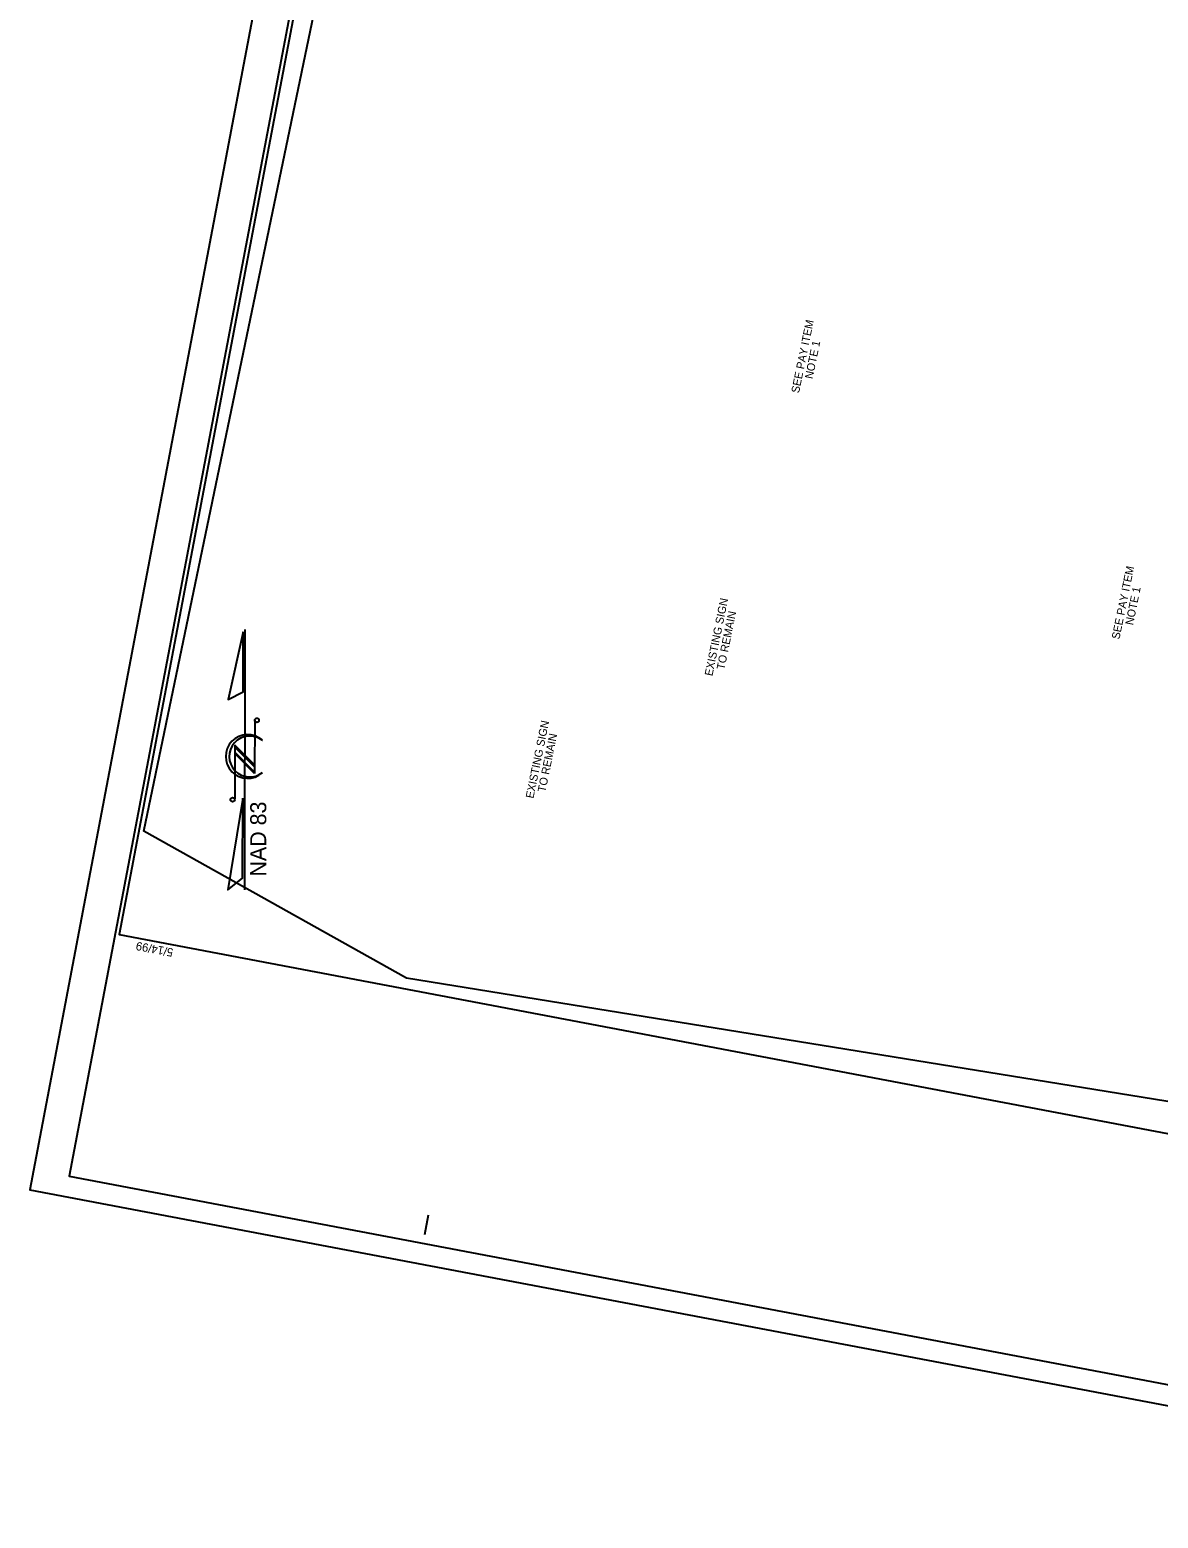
# Model space of a CAD drawing. Extents: x 1615681 to 1617075, y 899309 to 901168.
# Drawn here: x 1615681 to 1616385, y 899309 to 900239 of the extents above; entities that cross this region are included whole.
import ezdxf

# ---------------------------------------------------------------- set-up
doc = ezdxf.new("R2010")
doc.units = 0
for name, color, linetype in [('CTL Primary Horizontal and Vertical CELL', 7, 'Continuous'), ('CTL Primary Horizontal and Vertical Cogo Number', 7, 'Continuous'), ('CTL Secondary Horizontal and Vertical CELL', 7, 'Continuous'), ('Default', 7, 'Continuous'), ('Exist DTM Crownline Cogo Number', 7, 'Continuous'), ('Exist DTM Drainline Cogo Point CELL', 7, 'Continuous')]:
    doc.layers.add(name, color=color, linetype=linetype)

msp = doc.modelspace()

# ---------------------------------------------------------------- linework, layer by layer
at = {"layer": 'CTL Primary Horizontal and Vertical CELL'}
msp.add_lwpolyline([(1616015.87, 901159.82), (1615705.01, 899522.57), (1616741.59, 899325.76), (1617052.45, 900963.01)], close=True, dxfattribs=at)
at = {"layer": 'CTL Primary Horizontal and Vertical Cogo Number'}
msp.add_lwpolyline([(1615994.65, 901168.43), (1615680.53, 899513.99), (1616761.22, 899308.8), (1617075.34, 900963.24)], close=True, dxfattribs=at)
at = {"layer": 'CTL Secondary Horizontal and Vertical CELL'}
for p, q in [((1615736.43, 899674.38), (1615736.43, 899674.38)), ((1615927.13, 899486), (1615929.47, 899498.28))]:
    msp.add_line(p, q, dxfattribs=at)
msp.add_lwpolyline([(1616016.04, 901147.07), (1615736.24, 899673.39), (1616767.81, 899477.53), (1617047.61, 900951.21)], close=True, dxfattribs=at)
at = {"layer": 'Exist DTM Crownline Cogo Number'}
msp.add_lwpolyline([(1616176.29, 901060.7), (1617032.97, 900874.07), (1616753.23, 899510.43), (1615915.8, 899646.19), (1615751.76, 899738.03), (1615999.36, 900929.08), (1616157.93, 900902)], close=True, dxfattribs=at)
at = {"layer": 'Exist DTM Drainline Cogo Point CELL'}
for p, q in [((1615814.71, 899701.39), (1615814.88, 899863.89)), ((1615820.95, 899807.33), (1615820.91, 899773.98)), ((1615825.53, 899794.9), (1615825.71, 899794.78)), ((1615808.5, 899791.62), (1615808.47, 899757.72)), ((1615820.92, 899779.18), (1615808.5, 899791.62)), ((1615820.92, 899777.96), (1615808.5, 899790.39)), ((1615808.5, 899790.39), (1615808.5, 899787.34)), ((1615820.91, 899774.91), (1615808.5, 899787.34)), ((1615808.5, 899787.34), (1615820.91, 899774.91)), ((1615820.91, 899773.98), (1615808.5, 899786.42)), ((1615820.91, 899774.91), (1615820.92, 899777.96))]:
    msp.add_line(p, q, dxfattribs=at)
for points in [[(1615813.75, 899862.46), (1615804.43, 899820.27), (1615813.71, 899824.96)], [(1615813.45, 899758.64), (1615804.19, 899701.4), (1615813.39, 899708.64)]]:
    msp.add_lwpolyline(points, close=True, dxfattribs=at)
for centre in [(1615822.27, 899807.3), (1615807.15, 899757.67)]:
    msp.add_circle(centre, 1.33, dxfattribs=at)
for centre, radius, start, end in [((1615816.53, 899784.67), 13.65, 47.78125, 312.33529), ((1615817.84, 899784.67), 12.8, 53.03627, 308.56994)]:
    msp.add_arc(centre, radius, start, end, dxfattribs=at)

# ---------------------------------------------------------------- texts
at = {"layer": 'CTL Secondary Horizontal and Vertical CELL'}
msp.add_text('5/14/99', height=5.25, rotation=169.24937, dxfattribs=at).set_placement((1615770.4, 899664.62))
at = {"layer": 'Default'}
for s, p in [('SEE PAY ITEM', (1616160.72, 900011.35)), ('NOTE 1', (1616169.22, 900020.21)), ('SEE PAY ITEM', (1616360.74, 899857.55)), ('NOTE 1', (1616369.24, 899866.41)), ('EXISTING SIGN', (1616106.64, 899834.61)), ('TO REMAIN', (1616114.14, 899838.54)), ('EXISTING SIGN', (1615994.91, 899758.15)), ('TO REMAIN', (1616002.4, 899762.07))]:
    msp.add_text(s, height=5, rotation=78.45796, dxfattribs=at).set_placement(p)
at = {"layer": 'Exist DTM Drainline Cogo Point CELL'}
msp.add_text('NAD 83', height=10, rotation=89.94123, dxfattribs=at).set_placement((1615828.1, 899709.65))

doc.saveas('drawing.dxf')
